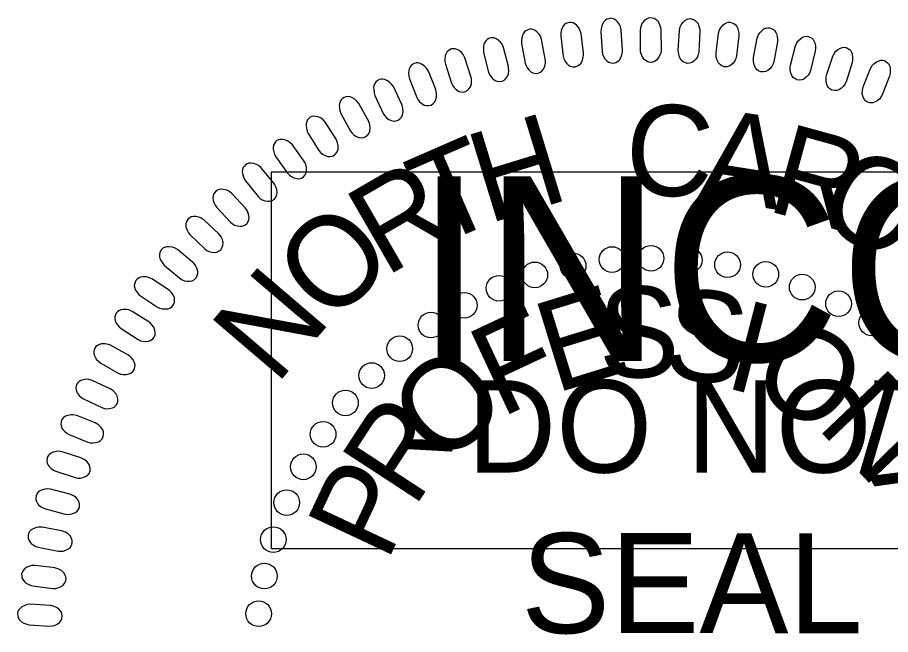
# Model space of a CAD drawing. Extents: x 505692 to 507376, y 438761 to 439861.
# Drawn here: x 507169.3 to 507223.8, y 439749.6 to 439788.1 of the extents above; entities that cross this region are included whole.
import ezdxf

# ---------------------------------------------------------------- set-up
doc = ezdxf.new("R2010")
doc.units = 0
doc.layers.add('Sheet PE Seal Cell', color=7, linetype='Continuous')
doc.layers.add('Sheet Sticker Incomplete CELL', color=7, linetype='Continuous')

msp = doc.modelspace()

# ---------------------------------------------------------------- linework, layer by layer
at = {"layer": 'Sheet PE Seal Cell'}
for points in [[(507207.097, 439786.058), (507207.02, 439787.283), (507206.969, 439787.499), (507206.909, 439787.635), (507206.786, 439787.798), (507206.682, 439787.901), (507206.565, 439787.974), (507206.459, 439788.007), (507206.345, 439788.02), (507206.235, 439787.993), (507206.117, 439787.956), (507206.016, 439787.89), (507205.918, 439787.783), (507205.864, 439787.7), (507205.805, 439787.546), (507205.757, 439787.364), (507205.745, 439787.203), (507205.816, 439785.948), (507205.849, 439785.781), (507205.902, 439785.644), (507206.001, 439785.49), (507206.123, 439785.358), (507206.224, 439785.284), (507206.385, 439785.234), (507206.535, 439785.224), (507206.682, 439785.273), (507206.783, 439785.33), (507206.904, 439785.437), (507207.013, 439785.613), (507207.068, 439785.797), (507207.091, 439785.928)], [(507208.212, 439786.067), (507208.213, 439787.294), (507208.25, 439787.513), (507208.303, 439787.654), (507208.415, 439787.823), (507208.512, 439787.932), (507208.624, 439788.012), (507208.729, 439788.052), (507208.841, 439788.072), (507208.953, 439788.052), (507209.073, 439788.022), (507209.177, 439787.962), (507209.282, 439787.862), (507209.342, 439787.782), (507209.409, 439787.633), (507209.469, 439787.453), (507209.491, 439787.294), (507209.498, 439786.037), (507209.476, 439785.868), (507209.431, 439785.728), (507209.341, 439785.569), (507209.229, 439785.428), (507209.132, 439785.349), (507208.974, 439785.289), (507208.825, 439785.27), (507208.676, 439785.309), (507208.571, 439785.359), (507208.444, 439785.459), (507208.324, 439785.629), (507208.257, 439785.808), (507208.227, 439785.938)], [(507210.572, 439786.041), (507210.649, 439787.265), (507210.7, 439787.482), (507210.761, 439787.618), (507210.884, 439787.78), (507210.987, 439787.883), (507211.105, 439787.956), (507211.212, 439787.989), (507211.325, 439788.002), (507211.435, 439787.975), (507211.553, 439787.937), (507211.654, 439787.871), (507211.752, 439787.765), (507211.806, 439787.682), (507211.864, 439787.528), (507211.912, 439787.345), (507211.925, 439787.185), (507211.853, 439785.93), (507211.82, 439785.762), (507211.766, 439785.626), (507211.666, 439785.472), (507211.546, 439785.34), (507211.444, 439785.266), (507211.283, 439785.216), (507211.133, 439785.206), (507210.986, 439785.255), (507210.885, 439785.312), (507210.764, 439785.419), (507210.656, 439785.596), (507210.6, 439785.779), (507210.578, 439785.911)], [(507202.278, 439785.488), (507202.048, 439786.692), (507201.97, 439786.901), (507201.893, 439787.029), (507201.751, 439787.174), (507201.635, 439787.264), (507201.51, 439787.321), (507201.4, 439787.341), (507201.286, 439787.34), (507201.179, 439787.299), (507201.068, 439787.247), (507200.976, 439787.169), (507200.891, 439787.051), (507200.848, 439786.961), (507200.81, 439786.802), (507200.785, 439786.615), (507200.792, 439786.454), (507201.02, 439785.218), (507201.074, 439785.055), (507201.144, 439784.927), (507201.262, 439784.787), (507201.399, 439784.67), (507201.509, 439784.61), (507201.674, 439784.581), (507201.825, 439784.59), (507201.964, 439784.657), (507202.058, 439784.725), (507202.164, 439784.847), (507202.25, 439785.035), (507202.282, 439785.225), (507202.287, 439785.357)], [(507204.659, 439785.856), (507204.505, 439787.073), (507204.441, 439787.286), (507204.372, 439787.418), (507204.239, 439787.572), (507204.129, 439787.669), (507204.008, 439787.734), (507203.899, 439787.76), (507203.785, 439787.766), (507203.676, 439787.732), (507203.562, 439787.688), (507203.465, 439787.615), (507203.374, 439787.503), (507203.325, 439787.417), (507203.276, 439787.26), (507203.239, 439787.074), (507203.237, 439786.913), (507203.387, 439785.666), (507203.43, 439785.5), (507203.492, 439785.367), (507203.601, 439785.22), (507203.73, 439785.096), (507203.836, 439785.029), (507203.999, 439784.988), (507204.15, 439784.987), (507204.294, 439785.046), (507204.391, 439785.109), (507204.505, 439785.223), (507204.602, 439785.406), (507204.646, 439785.593), (507204.66, 439785.725)], [(507212.934, 439785.866), (507213.088, 439787.083), (507213.153, 439787.296), (507213.222, 439787.427), (507213.355, 439787.582), (507213.465, 439787.679), (507213.587, 439787.743), (507213.695, 439787.77), (507213.809, 439787.776), (507213.918, 439787.741), (507214.032, 439787.697), (507214.129, 439787.624), (507214.22, 439787.512), (507214.269, 439787.426), (507214.318, 439787.269), (507214.354, 439787.083), (507214.356, 439786.922), (507214.206, 439785.674), (507214.162, 439785.509), (507214.1, 439785.377), (507213.991, 439785.229), (507213.862, 439785.105), (507213.756, 439785.038), (507213.593, 439784.998), (507213.442, 439784.997), (507213.298, 439785.056), (507213.201, 439785.118), (507213.087, 439785.233), (507212.99, 439785.416), (507212.946, 439785.603), (507212.933, 439785.736)], [(507215.273, 439785.58), (507215.504, 439786.784), (507215.582, 439786.993), (507215.659, 439787.12), (507215.801, 439787.265), (507215.917, 439787.355), (507216.042, 439787.412), (507216.152, 439787.432), (507216.267, 439787.431), (507216.373, 439787.39), (507216.485, 439787.338), (507216.576, 439787.259), (507216.66, 439787.142), (507216.704, 439787.053), (507216.742, 439786.893), (507216.767, 439786.705), (507216.759, 439786.544), (507216.531, 439785.308), (507216.476, 439785.146), (507216.406, 439785.018), (507216.288, 439784.878), (507216.152, 439784.762), (507216.042, 439784.701), (507215.876, 439784.672), (507215.726, 439784.681), (507215.586, 439784.748), (507215.493, 439784.816), (507215.387, 439784.938), (507215.301, 439785.127), (507215.269, 439785.316), (507215.264, 439785.449)], [(507199.972, 439785.015), (507199.668, 439786.204), (507199.577, 439786.407), (507199.492, 439786.53), (507199.341, 439786.666), (507199.219, 439786.748), (507199.091, 439786.797), (507198.979, 439786.81), (507198.866, 439786.801), (507198.762, 439786.755), (507198.654, 439786.695), (507198.568, 439786.612), (507198.491, 439786.489), (507198.453, 439786.397), (507198.425, 439786.235), (507198.412, 439786.047), (507198.429, 439785.887), (507198.734, 439784.667), (507198.798, 439784.509), (507198.876, 439784.385), (507199.003, 439784.252), (507199.146, 439784.145), (507199.26, 439784.092), (507199.427, 439784.072), (507199.577, 439784.091), (507199.712, 439784.166), (507199.801, 439784.24), (507199.899, 439784.369), (507199.972, 439784.563), (507199.993, 439784.754), (507199.99, 439784.886)], [(507217.579, 439785.106), (507217.884, 439786.294), (507217.975, 439786.496), (507218.06, 439786.619), (507218.211, 439786.756), (507218.332, 439786.837), (507218.461, 439786.887), (507218.572, 439786.899), (507218.686, 439786.891), (507218.789, 439786.844), (507218.898, 439786.785), (507218.984, 439786.701), (507219.06, 439786.578), (507219.099, 439786.486), (507219.127, 439786.324), (507219.14, 439786.136), (507219.123, 439785.975), (507218.816, 439784.756), (507218.752, 439784.598), (507218.674, 439784.474), (507218.547, 439784.342), (507218.404, 439784.234), (507218.29, 439784.181), (507218.123, 439784.162), (507217.974, 439784.18), (507217.839, 439784.256), (507217.75, 439784.331), (507217.652, 439784.459), (507217.578, 439784.653), (507217.558, 439784.843), (507217.561, 439784.976)], [(507219.828, 439784.483), (507220.208, 439785.65), (507220.312, 439785.848), (507220.404, 439785.964), (507220.564, 439786.091), (507220.69, 439786.164), (507220.821, 439786.206), (507220.933, 439786.211), (507221.046, 439786.196), (507221.146, 439786.142), (507221.251, 439786.076), (507221.332, 439785.987), (507221.4, 439785.86), (507221.432, 439785.766), (507221.45, 439785.603), (507221.452, 439785.413), (507221.424, 439785.255), (507221.042, 439784.058), (507220.969, 439783.903), (507220.882, 439783.784), (507220.748, 439783.66), (507220.598, 439783.562), (507220.481, 439783.516), (507220.313, 439783.508), (507220.164, 439783.536), (507220.035, 439783.619), (507219.951, 439783.699), (507219.861, 439783.833), (507219.8, 439784.031), (507219.791, 439784.223), (507219.803, 439784.356)], [(507197.639, 439784.395), (507197.26, 439785.562), (507197.157, 439785.759), (507197.064, 439785.875), (507196.905, 439786.002), (507196.779, 439786.077), (507196.648, 439786.118), (507196.535, 439786.124), (507196.423, 439786.108), (507196.322, 439786.055), (507196.218, 439785.989), (507196.137, 439785.9), (507196.068, 439785.773), (507196.036, 439785.678), (507196.018, 439785.515), (507196.016, 439785.326), (507196.044, 439785.167), (507196.425, 439783.97), (507196.499, 439783.815), (507196.585, 439783.697), (507196.719, 439783.572), (507196.869, 439783.474), (507196.986, 439783.428), (507197.154, 439783.42), (507197.302, 439783.447), (507197.432, 439783.531), (507197.516, 439783.611), (507197.606, 439783.745), (507197.668, 439783.943), (507197.676, 439784.134), (507197.665, 439784.267)], [(507195.438, 439783.578), (507194.987, 439784.719), (507194.871, 439784.91), (507194.772, 439785.02), (507194.605, 439785.137), (507194.474, 439785.203), (507194.34, 439785.236), (507194.228, 439785.234), (507194.117, 439785.211), (507194.02, 439785.151), (507193.919, 439785.08), (507193.844, 439784.986), (507193.783, 439784.855), (507193.758, 439784.759), (507193.75, 439784.595), (507193.76, 439784.406), (507193.798, 439784.249), (507194.253, 439783.078), (507194.336, 439782.929), (507194.43, 439782.815), (507194.572, 439782.7), (507194.727, 439782.611), (507194.847, 439782.572), (507195.015, 439782.575), (507195.162, 439782.612), (507195.285, 439782.704), (507195.364, 439782.788), (507195.446, 439782.928), (507195.496, 439783.129), (507195.491, 439783.321), (507195.472, 439783.453)], [(507222.112, 439783.749), (507222.564, 439784.889), (507222.68, 439785.079), (507222.779, 439785.19), (507222.946, 439785.306), (507223.077, 439785.372), (507223.211, 439785.405), (507223.323, 439785.404), (507223.434, 439785.381), (507223.531, 439785.321), (507223.631, 439785.249), (507223.706, 439785.155), (507223.767, 439785.023), (507223.793, 439784.927), (507223.801, 439784.764), (507223.791, 439784.575), (507223.752, 439784.418), (507223.296, 439783.247), (507223.212, 439783.098), (507223.12, 439782.984), (507222.978, 439782.87), (507222.822, 439782.78), (507222.702, 439782.742), (507222.534, 439782.745), (507222.388, 439782.782), (507222.264, 439782.873), (507222.184, 439782.958), (507222.103, 439783.098), (507222.055, 439783.3), (507222.058, 439783.491), (507222.078, 439783.623)], [(507193.32, 439782.646), (507192.799, 439783.756), (507192.671, 439783.938), (507192.564, 439784.043), (507192.391, 439784.149), (507192.256, 439784.206), (507192.121, 439784.231), (507192.009, 439784.222), (507191.899, 439784.193), (507191.806, 439784.127), (507191.711, 439784.049), (507191.642, 439783.951), (507191.589, 439783.816), (507191.569, 439783.718), (507191.572, 439783.554), (507191.594, 439783.366), (507191.642, 439783.212), (507192.17, 439782.072), (507192.262, 439781.928), (507192.362, 439781.821), (507192.511, 439781.715), (507192.672, 439781.636), (507192.794, 439781.605), (507192.962, 439781.618), (507193.105, 439781.663), (507193.224, 439781.763), (507193.297, 439781.852), (507193.37, 439781.997), (507193.406, 439782.201), (507193.39, 439782.392), (507193.362, 439782.522)], [(507191.237, 439781.632), (507190.646, 439782.707), (507190.508, 439782.882), (507190.396, 439782.979), (507190.216, 439783.073), (507190.078, 439783.123), (507189.941, 439783.139), (507189.83, 439783.123), (507189.722, 439783.087), (507189.634, 439783.016), (507189.543, 439782.932), (507189.48, 439782.829), (507189.436, 439782.691), (507189.422, 439782.592), (507189.435, 439782.429), (507189.469, 439782.242), (507189.526, 439782.092), (507190.125, 439780.987), (507190.226, 439780.849), (507190.333, 439780.748), (507190.488, 439780.652), (507190.654, 439780.583), (507190.777, 439780.56), (507190.944, 439780.583), (507191.084, 439780.638), (507191.196, 439780.744), (507191.264, 439780.838), (507191.327, 439780.987), (507191.35, 439781.193), (507191.323, 439781.383), (507191.287, 439781.511)], [(507189.22, 439780.49), (507188.563, 439781.526), (507188.414, 439781.691), (507188.295, 439781.781), (507188.11, 439781.865), (507187.969, 439781.905), (507187.832, 439781.912), (507187.722, 439781.89), (507187.616, 439781.846), (507187.532, 439781.77), (507187.447, 439781.68), (507187.391, 439781.574), (507187.356, 439781.434), (507187.348, 439781.334), (507187.371, 439781.172), (507187.418, 439780.988), (507187.483, 439780.841), (507188.15, 439779.776), (507188.26, 439779.645), (507188.373, 439779.551), (507188.534, 439779.464), (507188.703, 439779.406), (507188.828, 439779.391), (507188.993, 439779.425), (507189.13, 439779.488), (507189.235, 439779.601), (507189.296, 439779.7), (507189.351, 439779.852), (507189.36, 439780.059), (507189.321, 439780.247), (507189.277, 439780.372)], [(507187.22, 439779.135), (507186.498, 439780.128), (507186.339, 439780.283), (507186.215, 439780.366), (507186.025, 439780.437), (507185.882, 439780.469), (507185.744, 439780.467), (507185.636, 439780.438), (507185.534, 439780.388), (507185.455, 439780.306), (507185.375, 439780.212), (507185.326, 439780.102), (507185.3, 439779.96), (507185.298, 439779.86), (507185.332, 439779.699), (507185.388, 439779.519), (507185.464, 439779.377), (507186.196, 439778.356), (507186.315, 439778.232), (507186.433, 439778.145), (507186.599, 439778.068), (507186.771, 439778.021), (507186.897, 439778.014), (507187.059, 439778.058), (507187.192, 439778.13), (507187.29, 439778.25), (507187.345, 439778.351), (507187.389, 439778.507), (507187.386, 439778.714), (507187.335, 439778.899), (507187.283, 439779.022)], [(507185.339, 439777.746), (507184.557, 439778.692), (507184.389, 439778.837), (507184.259, 439778.911), (507184.065, 439778.97), (507183.921, 439778.993), (507183.783, 439778.983), (507183.677, 439778.947), (507183.578, 439778.891), (507183.504, 439778.804), (507183.431, 439778.705), (507183.388, 439778.592), (507183.371, 439778.448), (507183.376, 439778.349), (507183.42, 439778.19), (507183.487, 439778.014), (507183.572, 439777.876), (507184.367, 439776.904), (507184.492, 439776.787), (507184.616, 439776.708), (507184.786, 439776.643), (507184.962, 439776.606), (507185.088, 439776.607), (507185.247, 439776.661), (507185.375, 439776.741), (507185.464, 439776.867), (507185.513, 439776.971), (507185.548, 439777.129), (507185.532, 439777.336), (507185.469, 439777.517), (507185.41, 439777.637)], [(507183.551, 439776.207), (507182.712, 439777.102), (507182.535, 439777.236), (507182.4, 439777.303), (507182.203, 439777.349), (507182.057, 439777.363), (507181.921, 439777.344), (507181.817, 439777.302), (507181.722, 439777.24), (507181.654, 439777.148), (507181.587, 439777.044), (507181.551, 439776.929), (507181.543, 439776.785), (507181.554, 439776.686), (507181.608, 439776.531), (507181.687, 439776.359), (507181.779, 439776.228), (507182.634, 439775.306), (507182.766, 439775.197), (507182.895, 439775.127), (507183.069, 439775.072), (507183.247, 439775.046), (507183.372, 439775.054), (507183.528, 439775.118), (507183.65, 439775.206), (507183.732, 439775.338), (507183.774, 439775.446), (507183.799, 439775.605), (507183.77, 439775.81), (507183.696, 439775.988), (507183.629, 439776.102)], [(507181.889, 439774.598), (507180.995, 439775.438), (507180.809, 439775.561), (507180.672, 439775.618), (507180.471, 439775.653), (507180.325, 439775.657), (507180.19, 439775.63), (507180.09, 439775.581), (507179.998, 439775.513), (507179.936, 439775.418), (507179.876, 439775.31), (507179.848, 439775.193), (507179.848, 439775.048), (507179.866, 439774.95), (507179.928, 439774.798), (507180.019, 439774.632), (507180.119, 439774.506), (507181.03, 439773.64), (507181.169, 439773.541), (507181.301, 439773.478), (507181.479, 439773.434), (507181.658, 439773.42), (507181.782, 439773.436), (507181.934, 439773.509), (507182.05, 439773.605), (507182.123, 439773.741), (507182.159, 439773.851), (507182.174, 439774.013), (507182.132, 439774.216), (507182.047, 439774.388), (507181.973, 439774.498)], [(507180.275, 439772.811), (507179.331, 439773.593), (507179.138, 439773.704), (507178.997, 439773.753), (507178.795, 439773.775), (507178.648, 439773.77), (507178.516, 439773.734), (507178.418, 439773.679), (507178.331, 439773.605), (507178.275, 439773.507), (507178.222, 439773.395), (507178.201, 439773.277), (507178.211, 439773.132), (507178.234, 439773.035), (507178.307, 439772.888), (507178.407, 439772.727), (507178.515, 439772.608), (507179.479, 439771.802), (507179.624, 439771.71), (507179.76, 439771.656), (507179.94, 439771.624), (507180.119, 439771.621), (507180.242, 439771.645), (507180.389, 439771.728), (507180.499, 439771.83), (507180.564, 439771.971), (507180.592, 439772.083), (507180.597, 439772.245), (507180.542, 439772.444), (507180.447, 439772.611), (507180.366, 439772.717)], [(507178.751, 439771.109), (507177.721, 439771.775), (507177.516, 439771.862), (507177.371, 439771.894), (507177.167, 439771.892), (507177.022, 439771.87), (507176.895, 439771.819), (507176.805, 439771.753), (507176.727, 439771.669), (507176.682, 439771.564), (507176.643, 439771.447), (507176.636, 439771.327), (507176.663, 439771.185), (507176.698, 439771.092), (507176.787, 439770.954), (507176.905, 439770.806), (507177.027, 439770.701), (507178.078, 439770.013), (507178.233, 439769.939), (507178.374, 439769.902), (507178.557, 439769.89), (507178.735, 439769.909), (507178.855, 439769.947), (507178.991, 439770.046), (507179.088, 439770.161), (507179.136, 439770.308), (507179.151, 439770.423), (507179.136, 439770.584), (507179.059, 439770.776), (507178.945, 439770.93), (507178.852, 439771.026)], [(507177.537, 439769.086), (507176.501, 439769.743), (507176.296, 439769.83), (507176.15, 439769.861), (507175.946, 439769.857), (507175.802, 439769.833), (507175.675, 439769.782), (507175.585, 439769.715), (507175.508, 439769.63), (507175.465, 439769.525), (507175.426, 439769.408), (507175.42, 439769.288), (507175.448, 439769.146), (507175.483, 439769.053), (507175.574, 439768.915), (507175.693, 439768.769), (507175.816, 439768.665), (507176.873, 439767.985), (507177.028, 439767.913), (507177.17, 439767.875), (507177.352, 439767.866), (507177.53, 439767.886), (507177.65, 439767.925), (507177.785, 439768.026), (507177.881, 439768.141), (507177.928, 439768.288), (507177.942, 439768.403), (507177.926, 439768.565), (507177.847, 439768.756), (507177.732, 439768.909), (507177.638, 439769.004)], [(507176.233, 439767.037), (507175.158, 439767.628), (507174.948, 439767.701), (507174.8, 439767.723), (507174.598, 439767.706), (507174.455, 439767.674), (507174.331, 439767.615), (507174.246, 439767.542), (507174.174, 439767.453), (507174.138, 439767.345), (507174.106, 439767.226), (507174.108, 439767.106), (507174.145, 439766.966), (507174.186, 439766.875), (507174.285, 439766.744), (507174.413, 439766.605), (507174.542, 439766.508), (507175.639, 439765.896), (507175.799, 439765.834), (507175.943, 439765.806), (507176.126, 439765.808), (507176.302, 439765.838), (507176.419, 439765.885), (507176.547, 439765.994), (507176.636, 439766.116), (507176.673, 439766.266), (507176.681, 439766.381), (507176.654, 439766.541), (507176.563, 439766.727), (507176.439, 439766.872), (507176.339, 439766.961)], [(507175.124, 439764.913), (507174.014, 439765.435), (507173.8, 439765.496), (507173.651, 439765.508), (507173.45, 439765.478), (507173.309, 439765.437), (507173.19, 439765.37), (507173.109, 439765.292), (507173.043, 439765.199), (507173.013, 439765.089), (507172.99, 439764.968), (507172.999, 439764.849), (507173.045, 439764.711), (507173.092, 439764.623), (507173.198, 439764.498), (507173.335, 439764.367), (507173.47, 439764.279), (507174.604, 439763.737), (507174.767, 439763.685), (507174.912, 439763.667), (507175.094, 439763.679), (507175.269, 439763.722), (507175.382, 439763.775), (507175.504, 439763.892), (507175.585, 439764.019), (507175.612, 439764.171), (507175.612, 439764.287), (507175.576, 439764.444), (507175.474, 439764.625), (507175.34, 439764.762), (507175.235, 439764.844)], [(507174.185, 439762.794), (507173.045, 439763.246), (507172.827, 439763.292), (507172.678, 439763.295), (507172.479, 439763.253), (507172.341, 439763.203), (507172.226, 439763.128), (507172.15, 439763.045), (507172.09, 439762.949), (507172.068, 439762.837), (507172.051, 439762.715), (507172.068, 439762.596), (507172.122, 439762.462), (507172.174, 439762.376), (507172.289, 439762.259), (507172.434, 439762.138), (507172.574, 439762.058), (507173.739, 439761.588), (507173.905, 439761.547), (507174.051, 439761.537), (507174.232, 439761.561), (507174.404, 439761.614), (507174.514, 439761.675), (507174.628, 439761.799), (507174.701, 439761.93), (507174.719, 439762.084), (507174.711, 439762.2), (507174.665, 439762.355), (507174.552, 439762.528), (507174.409, 439762.657), (507174.299, 439762.732)], [(507173.309, 439760.605), (507172.143, 439760.984), (507171.922, 439761.016), (507171.773, 439761.01), (507171.577, 439760.956), (507171.443, 439760.897), (507171.332, 439760.815), (507171.263, 439760.729), (507171.209, 439760.628), (507171.193, 439760.515), (507171.184, 439760.392), (507171.209, 439760.274), (507171.271, 439760.144), (507171.329, 439760.062), (507171.45, 439759.951), (507171.602, 439759.84), (507171.747, 439759.769), (507172.94, 439759.372), (507173.108, 439759.342), (507173.255, 439759.342), (507173.434, 439759.377), (507173.601, 439759.441), (507173.708, 439759.508), (507173.813, 439759.639), (507173.878, 439759.775), (507173.886, 439759.93), (507173.871, 439760.044), (507173.816, 439760.197), (507173.692, 439760.362), (507173.542, 439760.482), (507173.428, 439760.551)], [(507172.605, 439758.349), (507171.416, 439758.655), (507171.195, 439758.673), (507171.046, 439758.658), (507170.854, 439758.591), (507170.724, 439758.524), (507170.618, 439758.436), (507170.554, 439758.344), (507170.507, 439758.24), (507170.498, 439758.127), (507170.497, 439758.003), (507170.529, 439757.887), (507170.6, 439757.761), (507170.662, 439757.683), (507170.791, 439757.58), (507170.949, 439757.479), (507171.098, 439757.417), (507172.313, 439757.096), (507172.483, 439757.076), (507172.63, 439757.085), (507172.806, 439757.132), (507172.969, 439757.206), (507173.071, 439757.28), (507173.168, 439757.417), (507173.225, 439757.557), (507173.223, 439757.711), (507173.201, 439757.826), (507173.136, 439757.974), (507173.002, 439758.131), (507172.845, 439758.241), (507172.726, 439758.302)], [(507172.094, 439756.053), (507170.889, 439756.284), (507170.666, 439756.288), (507170.519, 439756.264), (507170.331, 439756.185), (507170.205, 439756.11), (507170.106, 439756.015), (507170.047, 439755.92), (507170.006, 439755.814), (507170.006, 439755.7), (507170.012, 439755.576), (507170.051, 439755.463), (507170.13, 439755.341), (507170.197, 439755.267), (507170.331, 439755.173), (507170.496, 439755.08), (507170.648, 439755.028), (507171.882, 439754.785), (507172.053, 439754.776), (507172.198, 439754.794), (507172.371, 439754.852), (507172.53, 439754.935), (507172.626, 439755.016), (507172.714, 439755.159), (507172.762, 439755.302), (507172.751, 439755.457), (507172.721, 439755.569), (507172.648, 439755.712), (507172.504, 439755.862), (507172.34, 439755.961), (507172.218, 439756.015)], [(507171.673, 439753.739), (507170.456, 439753.893), (507170.234, 439753.884), (507170.088, 439753.85), (507169.906, 439753.76), (507169.785, 439753.678), (507169.692, 439753.576), (507169.639, 439753.477), (507169.605, 439753.368), (507169.611, 439753.255), (507169.626, 439753.132), (507169.672, 439753.021), (507169.758, 439752.905), (507169.83, 439752.835), (507169.97, 439752.749), (507170.14, 439752.668), (507170.296, 439752.625), (507171.541, 439752.46), (507171.713, 439752.461), (507171.856, 439752.488), (507172.026, 439752.557), (507172.178, 439752.651), (507172.27, 439752.738), (507172.349, 439752.885), (507172.388, 439753.032), (507172.367, 439753.184), (507172.33, 439753.295), (507172.248, 439753.433), (507172.094, 439753.573), (507171.924, 439753.663), (507171.8, 439753.708)], [(507171.387, 439751.395), (507170.163, 439751.473), (507169.941, 439751.449), (507169.798, 439751.406), (507169.622, 439751.305), (507169.506, 439751.215), (507169.42, 439751.108), (507169.373, 439751.006), (507169.346, 439750.895), (507169.36, 439750.782), (507169.382, 439750.661), (507169.434, 439750.553), (507169.527, 439750.442), (507169.603, 439750.377), (507169.748, 439750.301), (507169.924, 439750.229), (507170.082, 439750.197), (507171.335, 439750.11), (507171.506, 439750.122), (507171.648, 439750.158), (507171.813, 439750.238), (507171.959, 439750.34), (507172.045, 439750.432), (507172.115, 439750.585), (507172.144, 439750.733), (507172.114, 439750.885), (507172.07, 439750.993), (507171.979, 439751.126), (507171.817, 439751.256), (507171.642, 439751.335), (507171.515, 439751.372)]]:
    msp.add_lwpolyline(points, close=True, dxfattribs=at)
for centre in [(507206.441, 439772.972), (507208.869, 439773.051), (507211.258, 439772.93), (507204.012, 439772.574), (507213.647, 439772.651), (507201.623, 439772.017), (507216.035, 439772.052), (507218.304, 439771.255), (507199.393, 439771.181), (507220.573, 439770.218), (507197.219, 439770.121), (507195.148, 439768.886), (507222.643, 439769.023), (507193.197, 439767.413), (507191.444, 439765.74), (507189.811, 439764.028), (507188.417, 439762.076), (507187.182, 439760.045), (507186.146, 439757.814), (507185.31, 439755.504), (507184.752, 439753.234), (507184.392, 439750.883)]:
    msp.add_circle(centre, 0.801, dxfattribs=at)
at = {"layer": 'Sheet Sticker Incomplete CELL'}
msp.add_lwpolyline([(507185.195, 439754.938), (507185.195, 439778.438), (507332.195, 439778.438), (507332.195, 439754.938)], close=True, dxfattribs=at)

# ---------------------------------------------------------------- texts
at = {"layer": 'Sheet PE Seal Cell'}
for s, height, rotation, p in [('C', 5.669, 357.5877, (507207.187, 439777.062)), ('H', 5.669, 17.0557, (507198.682, 439775.179)), ('A', 5.669, 351.0983, (507211.763, 439776.854)), ('R', 5.669, 344.609, (507215.969, 439776.059)), ('T', 5.669, 23.5451, (507195.503, 439773.769)), ('O', 5.669, 331.6302, (507218.924, 439775.405)), ('R', 5.669, 30.0345, (507192.282, 439771.85)), ('O', 5.669, 43.0132, (507188.807, 439768.821)), ('N', 5.669, 49.5025, (507185.46, 439765.066)), ('E', 5.669, 17.1686, (507202.878, 439764.609)), ('S', 5.669, 1.289, (507205.646, 439765.569)), ('S', 5.669, 353.3492, (507209.506, 439765.67)), ('F', 5.669, 25.1084, (507199.488, 439763.071)), ('I', 5.669, 345.4094, (507213.307, 439765.039)), ('O', 5.669, 329.5298, (507214.81, 439764.867)), ('O', 5.669, 40.988, (507195.791, 439759.932)), ('N', 5.669, 313.6502, (507219.122, 439762.563)), ('R', 5.669, 56.8676, (507194.077, 439757.386)), ('P', 5.669, 64.8074, (507192.391, 439754.024)), ('A', 5.669, 297.7707, (507222.459, 439759.482)), ('SEAL', 6.2363, 359.9814, (507200.762, 439749.675))]:
    msp.add_text(s, height=height, rotation=rotation, dxfattribs=at).set_placement(p)
at = {"layer": 'Sheet Sticker Incomplete CELL'}
for s, height, p in [('INCOMPLETE PLANS', 11.52, (507194.145, 439766.638)), ('DO NOT USE FOR R/W ACQUISITION', 5.76, (507197.395, 439759.688))]:
    msp.add_text(s, height=height, dxfattribs=at).set_placement(p)

doc.saveas('drawing.dxf')
